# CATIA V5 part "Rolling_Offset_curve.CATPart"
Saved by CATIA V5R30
Part number: Part1
Bounding box of the stored display mesh (mm): x -34.79 to 141.747, y 0 to 36.041, z 0 to 120
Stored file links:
  D:\PROJECTS\CATIA V56R 2020\Resources\Parts File\c17_catia_v6_6r2020_prt\Rolling_Offset_curve.CATPart
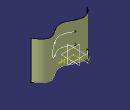
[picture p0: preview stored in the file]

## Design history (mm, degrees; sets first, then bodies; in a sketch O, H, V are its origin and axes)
Set1
  Sketch1 on xy-plane, origin (0, 0, 0), H (1, 0, 0), V (0, 1, 0)
    spline S1 through (141.7471, 7.6193) (96.894, 32.921) (61.2417, 14.2322) (16.9636, 29.4707) (-34.7899, 9.0569)
  Extrude1: Element1 Sketch1, Lim1 120, Lim2 0
  Plane1: type Offset, RefPlane zx-plane, Offset 75
  Sketch2 on Plane1, origin (0, 75, 0), H (-1, 0, 0), V (0, 0, 1)
    line L1 (-21.0945, 87.991) -> (-85.0485, 87.991)
    arc A1 centre (-85.0485, 70.1055) radius 17.8854 from (-85.0485, 87.991) to (-85.0485, 52.2201) ccw
    line L2 (-85.0485, 52.2201) -> (-21.0945, 52.2201)
    horizontal: L1 H
    tangency: A1 L1, L2 A1
  Project1: ToProject Sketch2, Support Extrude1, Direction zx-plane
Body1 (main body)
